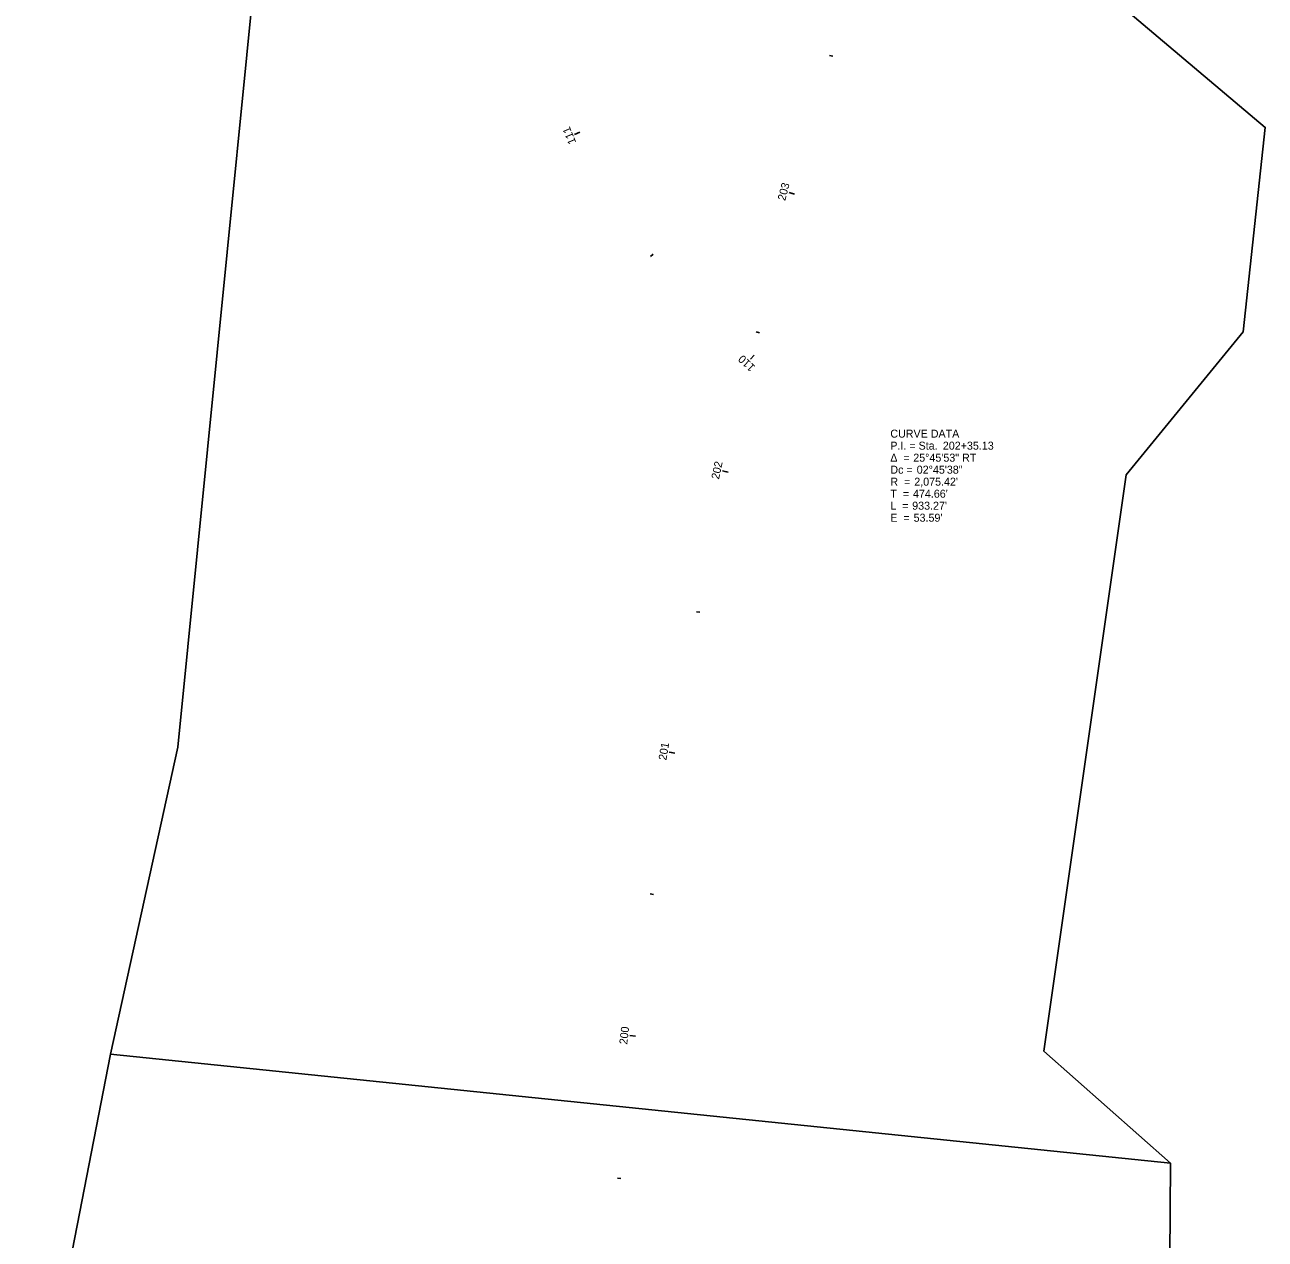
# Model space of a CAD drawing. Extents: x 1564517 to 1565226, y 635740 to 637455.
# Drawn here: x 1564587.2 to 1565021.2, y 636164.7 to 636589.4 of the extents above; entities that cross this region are included whole.
import ezdxf

# ---------------------------------------------------------------- set-up
doc = ezdxf.new("R2010")
doc.units = 0
for name, color, linetype in [('GE_P_Alignment_1000_Curve_Data', 7, 'Continuous'), ('GE_P_Alignment_1000_Stations', 7, 'Continuous'), ('GE_P_Alignment_100_Curve_Data', 7, 'Continuous'), ('GE_P_Alignment_100_Stations', 7, 'Continuous'), ('GE_P_Alignment_500_Curve_Data', 7, 'Continuous'), ('GE_P_Alignment_500_Stations', 7, 'Continuous'), ('SH_Named_Boundary', 7, 'Continuous')]:
    doc.layers.add(name, color=color, linetype=linetype)

msp = doc.modelspace()

# ---------------------------------------------------------------- linework, layer by layer
at = {"layer": 'GE_P_Alignment_1000_Stations'}
msp.add_line((1564800.84, 636235.64), (1564798.85, 636235.87), dxfattribs=at)
at = {"layer": 'GE_P_Alignment_100_Stations'}
for p, q in [((1564869.9, 636578.34), (1564868.75, 636578.67)), ((1564781.38, 636551.81), (1564779.54, 636551.05)), ((1564856.51, 636530.17), (1564854.58, 636530.68)), ((1564807.02, 636509.1), (1564806.1, 636508.34)), ((1564844.29, 636481.69), (1564843.12, 636481.96)), ((1564842.42, 636473.84), (1564841.05, 636472.39)), ((1564833.23, 636432.92), (1564831.27, 636433.34)), ((1564823.35, 636383.91), (1564822.17, 636384.13)), ((1564814.66, 636334.67), (1564812.68, 636335)), ((1564807.15, 636285.24), (1564805.96, 636285.41)), ((1564800.84, 636235.64), (1564798.85, 636235.87)), ((1564795.72, 636185.91), (1564794.53, 636186.02))]:
    msp.add_line(p, q, dxfattribs=at)
at = {"layer": 'GE_P_Alignment_500_Stations'}
for p, q in [((1564856.51, 636530.17), (1564855.35, 636530.47)), ((1564833.23, 636432.92), (1564832.06, 636433.18)), ((1564814.66, 636334.67), (1564813.47, 636334.87)), ((1564800.84, 636235.64), (1564798.85, 636235.87))]:
    msp.add_line(p, q, dxfattribs=at)
at = {"layer": 'SH_Named_Boundary'}
for points in [[(1564617.12, 636229.41), (1564988.09, 636191.25), (1564943.69, 636230.5), (1564972.57, 636431.98), (1565013.42, 636482), (1565021.18, 636553.46), (1564968.04, 636598.47), (1565001.39, 636689.39), (1564864.83, 636740.08), (1564842.01, 636748.56), (1564682.06, 636752.05), (1564640.72, 636336.77)], [(1564658.34, 635750.59), (1564898, 635751.43), (1564898, 635751.43), (1564898, 635751.43), (1564956.75, 635750.68), (1564987.45, 635750.7), (1564987.39, 635815.7), (1564987.33, 635880.7), (1564987.28, 635945.7), (1564987.22, 636010.7), (1564987.17, 636075.7), (1564988.09, 636191.25), (1564617.12, 636229.41), (1564587.17, 636075.36), (1564587.22, 636010.36), (1564660.39, 635967.97), (1564659.6, 635859.64), (1564658.34, 635750.59), (1564658.34, 635750.59)]]:
    msp.add_lwpolyline(points, close=True, dxfattribs=at)

# ---------------------------------------------------------------- texts
at = {"layer": 'GE_P_Alignment_1000_Curve_Data'}
for s, p in [('CURVE DATA', (1564890.01, 636444.99)), ('P.I. = Sta. ', (1564890.01, 636440.79)), ('202+35.13', (1564908.38, 636440.79)), ('Δ  = ', (1564890.01, 636436.59)), ('25°45\'53" RT', (1564898.03, 636436.59)), ('Dc = ', (1564890.01, 636432.39)), ('02°45\'38"', (1564899.25, 636432.39)), ('R  = ', (1564890.01, 636428.19)), ("2,075.42'", (1564898.38, 636428.19)), ('T  = ', (1564890.01, 636423.99)), ("474.66'", (1564897.94, 636423.99)), ('L  = ', (1564890.01, 636419.79)), ("933.27'", (1564897.66, 636419.79)), ('E  = ', (1564890.01, 636415.59)), ("53.59'", (1564898.16, 636415.59))]:
    msp.add_text(s, height=2.8, dxfattribs=at).set_placement(p)
at = {"layer": 'GE_P_Alignment_1000_Stations'}
msp.add_text('200', height=2.8, rotation=83.4365, dxfattribs=at).set_placement((1564797.93, 636232.68))
at = {"layer": 'GE_P_Alignment_100_Curve_Data'}
for s, p in [('CURVE DATA', (1564890.01, 636444.99)), ('P.I. = Sta. ', (1564890.01, 636440.79)), ('202+35.13', (1564908.38, 636440.79)), ('Δ  = ', (1564890.01, 636436.59)), ('25°45\'53" RT', (1564898.03, 636436.59)), ('Dc = ', (1564890.01, 636432.39)), ('02°45\'38"', (1564899.25, 636432.39)), ('R  = ', (1564890.01, 636428.19)), ("2,075.42'", (1564898.38, 636428.19)), ('T  = ', (1564890.01, 636423.99)), ("474.66'", (1564897.94, 636423.99)), ('L  = ', (1564890.01, 636419.79)), ("933.27'", (1564897.66, 636419.79)), ('E  = ', (1564890.01, 636415.59)), ("53.59'", (1564898.16, 636415.59))]:
    msp.add_text(s, height=2.8, dxfattribs=at).set_placement(p)
at = {"layer": 'GE_P_Alignment_100_Stations'}
for s, rotation, p in [('111', 112.474, (1564780.15, 636548.25)), ('203', 75.1544, (1564853.21, 636527.66)), ('110', 136.6192, (1564842.95, 636469.84)), ('202', 77.9151, (1564830.05, 636430.26)), ('201', 80.6758, (1564811.64, 636332.02)), ('200', 83.4365, (1564797.93, 636232.68))]:
    msp.add_text(s, height=2.8, rotation=rotation, dxfattribs=at).set_placement(p)
at = {"layer": 'GE_P_Alignment_500_Curve_Data'}
for s, p in [('CURVE DATA', (1564890.01, 636444.99)), ('P.I. = Sta. ', (1564890.01, 636440.79)), ('202+35.13', (1564908.38, 636440.79)), ('Δ  = ', (1564890.01, 636436.59)), ('25°45\'53" RT', (1564898.03, 636436.59)), ('Dc = ', (1564890.01, 636432.39)), ('02°45\'38"', (1564899.25, 636432.39)), ('R  = ', (1564890.01, 636428.19)), ("2,075.42'", (1564898.38, 636428.19)), ('T  = ', (1564890.01, 636423.99)), ("474.66'", (1564897.94, 636423.99)), ('L  = ', (1564890.01, 636419.79)), ("933.27'", (1564897.66, 636419.79)), ('E  = ', (1564890.01, 636415.59)), ("53.59'", (1564898.16, 636415.59))]:
    msp.add_text(s, height=2.8, dxfattribs=at).set_placement(p)
at = {"layer": 'GE_P_Alignment_500_Stations'}
msp.add_text('200', height=2.8, rotation=83.4365, dxfattribs=at).set_placement((1564797.93, 636232.68))

doc.saveas('drawing.dxf')
